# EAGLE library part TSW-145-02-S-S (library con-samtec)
THROUGH-HOLE .025" SQ POST HEADER Source: Samtec TSW.pdf
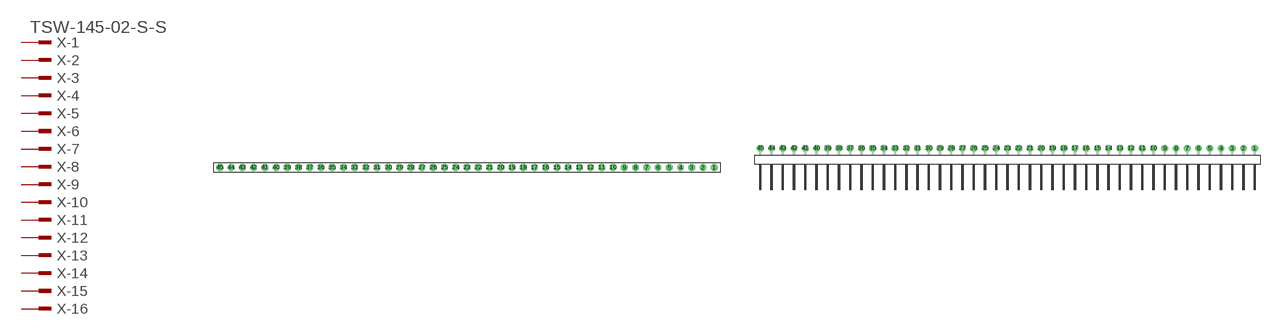
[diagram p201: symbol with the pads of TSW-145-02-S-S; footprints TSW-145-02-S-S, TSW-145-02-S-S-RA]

Designator prefix X; gates -1=MPINV -2=MPIN -3=MPIN -4=MPIN -5=MPIN -6=MPIN -7=MPIN -8=MPIN -9=MPIN -10=MPIN -11=MPIN -12=MPIN -13=MPIN -14=MPIN -15=MPIN -16=MPIN -17=MPIN -18=MPIN -19=MPIN -20=MPIN -21=MPIN -22=MPIN -23=MPIN -24=MPIN -25=MPIN -26=MPIN -27=MPIN -28=MPIN -29=MPIN -30=MPIN -31=MPIN -32=MPIN -33=MPIN -34=MPIN -35=MPIN -36=MPIN -37=MPIN -38=MPIN -39=MPIN -40=MPIN -41=MPIN -42=MPIN -43=MPIN -44=MPIN -45=MPIN

## TSW-145-02-S-S (OC_FARNELL: unknown; OC_NEWARK: unknown)  [TSW-145-02-S-S]
1  -1:1  pas
2  -2:1  pas
3  -3:1  pas
4  -4:1  pas
5  -5:1  pas
6  -6:1  pas
7  -7:1  pas
8  -8:1  pas
9  -9:1  pas
10  -10:1  pas
11  -11:1  pas
12  -12:1  pas
13  -13:1  pas
14  -14:1  pas
15  -15:1  pas
16  -16:1  pas
17  -17:1  pas
18  -18:1  pas
19  -19:1  pas
20  -20:1  pas
21  -21:1  pas
22  -22:1  pas
23  -23:1  pas
24  -24:1  pas
25  -25:1  pas
26  -26:1  pas
27  -27:1  pas
28  -28:1  pas
29  -29:1  pas
30  -30:1  pas
31  -31:1  pas
32  -32:1  pas
33  -33:1  pas
34  -34:1  pas
35  -35:1  pas
36  -36:1  pas
37  -37:1  pas
38  -38:1  pas
39  -39:1  pas
40  -40:1  pas
41  -41:1  pas
42  -42:1  pas
43  -43:1  pas
44  -44:1  pas
45  -45:1  pas

## TSW-145-02-S-S-RA (OC_FARNELL: unknown; OC_NEWARK: unknown)  [TSW-145-02-S-S-RA]
Pads as for TSW-145-02-S-S

## Footprint TSW-145-02-S-S (pad centres in mm)
THROUGH-HOLE .025" SQ POST HEADER Source: Samtec TSW.pdf
drill 1 pad 1.5 octagon: 1 55.88,0; 2 53.34,0; 3 50.8,0; 4 48.26,0; 5 45.72,0; 6 43.18,0; 7 40.64,0; 8 38.1,0; 9 35.56,0; 10 33.02,0; 11 30.48,0; 12 27.94,0; 13 25.4,0; 14 22.86,0; 15 20.32,0; 16 17.78,0; 17 15.24,0; 18 12.7,0; 19 10.16,0; 20 7.62,0; 21 5.08,0; 22 2.54,0; 23 0,0; 24 -2.54,0; 25 -5.08,0; 26 -7.62,0; 27 -10.16,0; 28 -12.7,0; 29 -15.24,0; 30 -17.78,0; 31 -20.32,0; 32 -22.86,0; 33 -25.4,0; 34 -27.94,0; 35 -30.48,0; 36 -33.02,0; 37 -35.56,0; 38 -38.1,0; 39 -40.64,0; 40 -43.18,0; 41 -45.72,0; 42 -48.26,0; 43 -50.8,0; 44 -53.34,0; 45 -55.88,0

## Footprint TSW-145-02-S-S-RA (pad centres in mm)
THROUGH-HOLE .025" SQ POST HEADER Source: Samtec TSW.pdf
drill 1 pad 1.5 octagon: 1 55.88,1.524; 2 53.34,1.524; 3 50.8,1.524; 4 48.26,1.524; 5 45.72,1.524; 6 43.18,1.524; 7 40.64,1.524; 8 38.1,1.524; 9 35.56,1.524; 10 33.02,1.524; 11 30.48,1.524; 12 27.94,1.524; 13 25.4,1.524; 14 22.86,1.524; 15 20.32,1.524; 16 17.78,1.524; 17 15.24,1.524; 18 12.7,1.524; 19 10.16,1.524; 20 7.62,1.524; 21 5.08,1.524; 22 2.54,1.524; 23 0,1.524; 24 -2.54,1.524; 25 -5.08,1.524; 26 -7.62,1.524; 27 -10.16,1.524; 28 -12.7,1.524; 29 -15.24,1.524; 30 -17.78,1.524; 31 -20.32,1.524; 32 -22.86,1.524; 33 -25.4,1.524; 34 -27.94,1.524; 35 -30.48,1.524; 36 -33.02,1.524; 37 -35.56,1.524; 38 -38.1,1.524; 39 -40.64,1.524; 40 -43.18,1.524; 41 -45.72,1.524; 42 -48.26,1.524; 43 -50.8,1.524; 44 -53.34,1.524; 45 -55.88,1.524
